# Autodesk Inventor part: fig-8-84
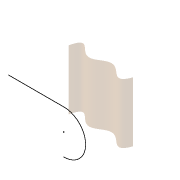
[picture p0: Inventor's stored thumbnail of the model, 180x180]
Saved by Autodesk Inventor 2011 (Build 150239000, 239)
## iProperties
Shininess: 64.0
Length Units: 11269
Angle Units: 11279
Time Units: 11290
Mass Units: 11283
Length Display Precision: 3
Angle Display Precision: 2
Compacted: True
Part Number: fig-8-84
Document SubType Name: Modeling
Created: 2003-08
Designer: Owner
Manufacturer: Standard
Standards Organization: Custom
Density: 1 g/cm^3
Density: 0.0
Volumn: 0.0
Area: 0.0
PropertySet Name: Model Information
Control State: 0
Master: False
Checked Out: False
Author: Owner
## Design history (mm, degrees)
sketch "Sketch1"
  geometry: 7 further points
  constraints: 7 other
  dimensions: "d0" = 80 horizontal distance of point (40, 1.742) point (-40, -4.065); "d1" = 40 horizontal distance of point (0, 0) point (-40, -4.065)
extrude_surface "ExtrusionSrf1" sketch "Sketch1" dims "d2" = 80, "d3" = 0
sketch "Sketch2"
  geometry: L1 (40, 0)-(40, -40) reference; L2 (-40, 0)-(-40, -40) reference; 7 further points
  constraints: 2 point on line, 7 other
extrude_surface "ExtrusionSrf2" sketch "Sketch2" dims "d4" = 80, "d5" = 0
workplane "Work Plane1"
sketch "Sketch4"
  geometry: L1 (70.027, 16.004)-(-4, 16.004); A1 r 29.004 centre (-4, -13) between (-4, 16.004) and (-2.981, -41.986)
  constraints: 2 end point, 2 point on circle, 1 centre point, 1 horizontal, 1 tangent
body "Srf1"
body "Srf2"
other parameters: "d6" = -54.75
